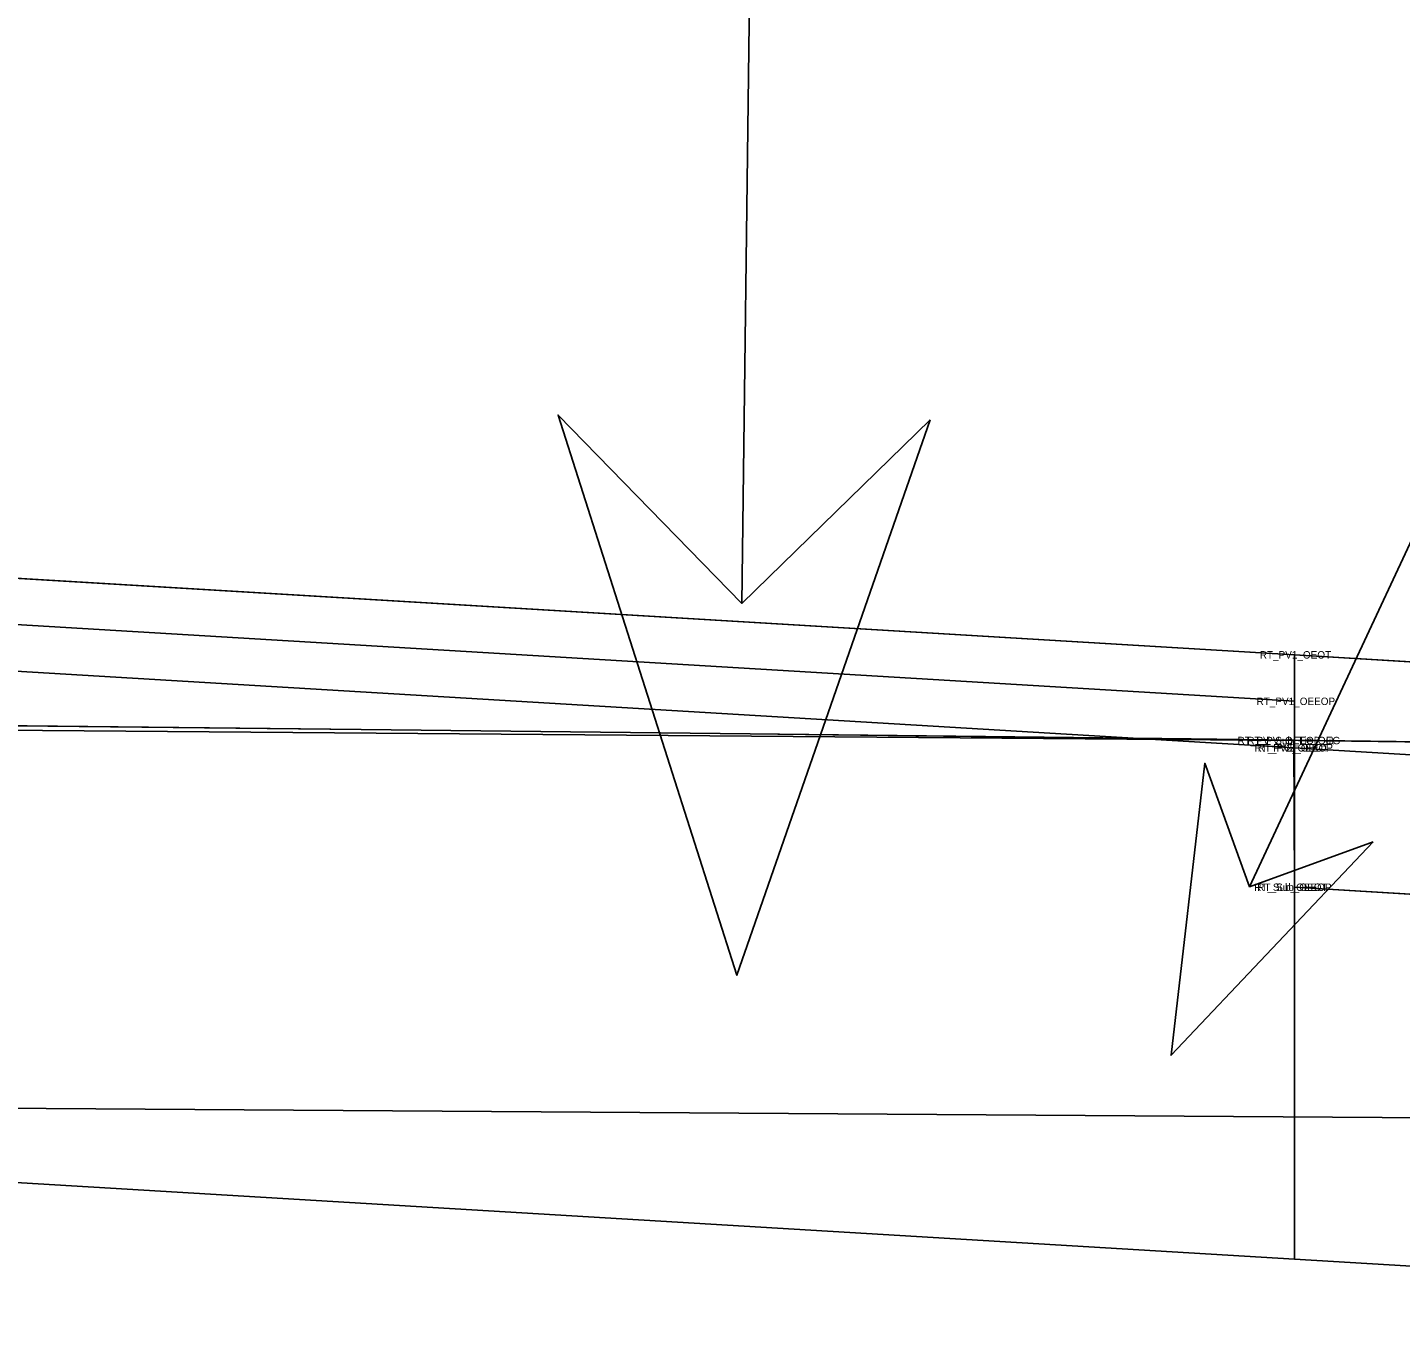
# Model space of a CAD drawing. Extents: x -516 to 303, y -10 to 5017.
# Drawn here: x 158.595 to 162.285, y 3003.089 to 3006.561 of the extents above; entities that cross this region are included whole.
import ezdxf

# ---------------------------------------------------------------- set-up
doc = ezdxf.new("R2010")
doc.units = 0
for name, color, linetype in [('Exist CMT Pavement', 7, 'Continuous'), ('Exist XS Ground Line', 7, 'Continuous'), ('Misc Plan Tools Cell', 7, 'Continuous'), ('Prop CMT Pvmt Course 1', 7, 'Continuous'), ('Prop CMT Pvmt Course 1 Wedge', 7, 'Continuous'), ('Prop CMT Pvmt Course 2', 7, 'Continuous'), ('Prop CMT Pvmt Course 2 Wedge', 7, 'Continuous'), ('Prop CMT Pvmt Course 3', 7, 'Continuous'), ('Prop CMT Pvmt Course 3 Wedge', 7, 'Continuous'), ('Prop CMT Pvmt Surface', 7, 'Continuous'), ('Prop CMT Pvmt Surface Shoulder', 7, 'Continuous'), ('Prop CMT Pvmt Wedge Surface 1', 7, 'Continuous'), ('Prop CMT Pvmt Wedge Surface 2', 7, 'Continuous'), ('Prop CMT Pvmt Wedge Surface 3', 7, 'Continuous'), ('Prop CMT Shld Paved Course 1', 7, 'Continuous'), ('Prop CMT Shld Paved Course 2', 7, 'Continuous'), ('Prop CMT Shld Paved Course 3', 7, 'Continuous'), ('Prop CMT Subgrade Earthwork', 7, 'Continuous'), ('Prop Road Sect_ Material - Bubble + Leader + Bubble Tx', 7, 'Continuous'), ('Prop Road Sect_ Material - Contact (General - Major)', 7, 'Continuous'), ('Prop Road Sect_ Misc - Drafting Aid (solid line)', 7, 'Continuous'), ('Prop Road Sect_ Misc - Drafting Aid (Tx - small)', 7, 'Continuous'), ('Prop Road Sect_ Recs - UC Shallow (Outline)', 7, 'Continuous'), ('Prop Road Sect_ Recs - UC Shallow (Pattern)', 7, 'Continuous'), ('Scratch_Level_0', 7, 'Continuous')]:
    doc.layers.add(name, color=color, linetype=linetype)

msp = doc.modelspace()

# ---------------------------------------------------------------- linework, layer by layer
at = {"layer": 'Exist CMT Pavement'}
msp.add_lwpolyline([(150.0015, 3004.7392), (161.9985, 3004.6435)], dxfattribs=at)
at = {"layer": 'Exist XS Ground Line'}
msp.add_lwpolyline([(127.6717, 3004.8956), (129.9724, 3004.8801), (136.1955, 3004.6894), (149.2025, 3004.7517), (149.5824, 3004.7536), (150.2842, 3004.7329), (152.2526, 3004.7198), (152.8486, 3004.7093), (154.5021, 3004.7218), (155.1545, 3004.7264), (155.8812, 3004.7161), (157.8066, 3004.6912), (159.4913, 3004.6732), (160.5369, 3004.6613), (161.7241, 3004.6468), (162.7917, 3004.6337), (163.3101, 3004.6258), (163.611, 3004.6229), (164.8225, 3004.6077), (165.5966, 3004.5986), (166.1809, 3004.5801)], dxfattribs=at)
at = {"layer": 'Misc Plan Tools Cell'}
msp.add_lwpolyline([(161.0208, 3005.5059), (160.5017, 3004.0124), (160.0208, 3005.5187), (160.5144, 3005.0123)], close=True, dxfattribs=at)
at = {"layer": 'Prop CMT Pvmt Course 1'}
for points in [[(150, 3005.594), (162, 3004.874)], [(162, 3004.749), (150, 3005.469)], [(162, 3004.874), (162, 3004.624), (162, 3004.624), (162, 3004.749)]]:
    msp.add_lwpolyline(points, dxfattribs=at)
at = {"layer": 'Prop CMT Pvmt Course 1 Wedge'}
msp.add_lwpolyline([(150, 3005.469), (162, 3004.749)], dxfattribs=at)
at = {"layer": 'Prop CMT Pvmt Course 2'}
msp.add_lwpolyline([(162, 3004.624), (162, 3004.624), (162, 3004.624)], close=True, dxfattribs=at)
msp.add_lwpolyline([(162, 3004.624), (162, 3004.624)], dxfattribs=at)
at = {"layer": 'Prop CMT Pvmt Course 2 Wedge'}
msp.add_lwpolyline([(150, 3005.344), (162, 3004.624)], dxfattribs=at)
at = {"layer": 'Prop CMT Pvmt Course 3'}
for points in [[(162, 3004.624), (162, 3004.624), (162, 3004.249), (162, 3004.249)], [(162, 3004.249), (162, 3004.624)]]:
    msp.add_lwpolyline(points, dxfattribs=at)
at = {"layer": 'Prop CMT Pvmt Course 3 Wedge'}
msp.add_lwpolyline([(150, 3005.344), (162, 3004.624)], dxfattribs=at)
at = {"layer": 'Prop CMT Pvmt Surface'}
msp.add_line((150, 3005.594), (162, 3004.874), dxfattribs=at)
at = {"layer": 'Prop CMT Pvmt Surface Shoulder'}
msp.add_line((162, 3004.874), (164, 3004.754), dxfattribs=at)
at = {"layer": 'Prop CMT Pvmt Wedge Surface 1'}
for points in [[(150, 3005.469), (162, 3004.749)], [(162, 3004.624), (162, 3004.874)], [(162, 3004.749), (162, 3004.624), (162, 3004.624)]]:
    msp.add_lwpolyline(points, dxfattribs=at)
at = {"layer": 'Prop CMT Pvmt Wedge Surface 2'}
for points in [[(150, 3005.344), (162, 3004.624)], [(162, 3004.624), (162, 3004.874)]]:
    msp.add_lwpolyline(points, dxfattribs=at)
at = {"layer": 'Prop CMT Pvmt Wedge Surface 3'}
for points in [[(150, 3005.344), (162, 3004.624)], [(162, 3004.624), (162, 3004.874)]]:
    msp.add_lwpolyline(points, dxfattribs=at)
at = {"layer": 'Prop CMT Shld Paved Course 1'}
for points in [[(162, 3004.874), (164, 3004.754), (164.266, 3004.488)], [(162, 3004.624), (162, 3004.874)], [(164.266, 3004.488), (162, 3004.624)]]:
    msp.add_lwpolyline(points, dxfattribs=at)
at = {"layer": 'Prop CMT Shld Paved Course 2'}
for points in [[(162, 3004.624), (164.266, 3004.488)], [(164.266, 3004.488), (162, 3004.624)], [(162, 3004.624), (162, 3004.624)]]:
    msp.add_lwpolyline(points, dxfattribs=at)
at = {"layer": 'Prop CMT Shld Paved Course 3'}
for points in [[(162, 3004.624), (164.266, 3004.488)], [(162, 3004.249), (162, 3004.624)], [(164.6649, 3004.0891), (162, 3004.249)]]:
    msp.add_lwpolyline(points, dxfattribs=at)
at = {"layer": 'Prop CMT Subgrade Earthwork'}
for q in [(161.9985, 3004.6435), (164.6649, 3004.0891), (162, 3004.249)]:
    msp.add_line((162, 3004.249), q, dxfattribs=at)
at = {"layer": 'Prop Road Sect_ Material - Bubble + Leader + Bubble Tx'}
msp.add_line((160.5489, 3007.7169), (160.5144, 3005.0123), dxfattribs=at)
at = {"layer": 'Prop Road Sect_ Material - Contact (General - Major)'}
msp.add_line((178.8965, 3003.5176), (2.4565, 3004.7053), dxfattribs=at)
at = {"layer": 'Prop Road Sect_ Misc - Drafting Aid (solid line)'}
msp.add_line((162, 3004.249), (162, 3003.249), dxfattribs=at)
at = {"layer": 'Prop Road Sect_ Misc - Drafting Aid (Tx - small)'}
msp.add_line((163.9214, 3008.6281), (161.8797, 3004.2503), dxfattribs=at)
msp.add_lwpolyline([(162.2119, 3004.3712), (161.6684, 3003.7972), (161.7588, 3004.5825), (161.8797, 3004.2503)], close=True, dxfattribs=at)
at = {"layer": 'Prop Road Sect_ Recs - UC Shallow (Outline)'}
msp.add_lwpolyline([(165.6772, 3004.596), (165.5966, 3004.5986), (164.8225, 3004.6077), (161.7224, 3004.6479), (160.5369, 3004.6613), (159.4913, 3004.6732), (157.8066, 3004.6912), (155.8812, 3004.7161), (155.1545, 3004.7264), (154.5021, 3004.7218), (152.8486, 3004.7093), (149.9985, 3004.7392), (148, 3004.746), (145.4104, 3004.7336), (144.4104, 3004.7288), (144.4104, 3004.2444), (145.4104, 3004.2444), (148, 3004.089), (162, 3003.249), (164.6649, 3003.0891), (165.6649, 3003.0891), (165.6649, 3004.0891), (165.6772, 3004.596)], dxfattribs=at)
at = {"layer": 'Prop Road Sect_ Recs - UC Shallow (Pattern)'}
msp.add_lwpolyline([(165.6772, 3004.596), (165.5966, 3004.5986), (164.8225, 3004.6077), (161.7224, 3004.6479), (160.5369, 3004.6613), (159.4913, 3004.6732), (157.8066, 3004.6912), (155.8812, 3004.7161), (155.1545, 3004.7264), (154.5021, 3004.7218), (152.8486, 3004.7093), (149.9985, 3004.7392), (148, 3004.746), (145.4104, 3004.7336), (144.4104, 3004.7288), (144.4104, 3004.2444), (145.4104, 3004.2444), (148, 3004.089), (162, 3003.249), (164.6649, 3003.0891), (165.6649, 3003.0891), (165.6649, 3004.0891), (165.6772, 3004.596)], dxfattribs=at)

# ---------------------------------------------------------------- texts
at = {"layer": 'Scratch_Level_0'}
for s, p in [('RT_PV1_OEOT', (161.9069, 3004.864)), ('RT_PV1_OEEOP', (161.8983, 3004.739)), ('RT_PV_Sub_Tie_Out', (161.8475, 3004.6335)), ('RT_PV_OEEOP_EG', (161.8735, 3004.6335)), ('RT_PV2_OEEOP', (161.8926, 3004.614)), ('RT_PV3_OEEOP', (161.8926, 3004.614)), ('RT_PV3_OEOT', (161.9013, 3004.614)), ('RT_PV2_OEOT', (161.9013, 3004.614)), ('RT_Sub_OEEOP', (161.8917, 3004.239)), ('RT_Sub_OEOT', (161.9003, 3004.239))]:
    msp.add_text(s, height=0.02, dxfattribs=at).set_placement(p)

doc.saveas('drawing.dxf')
